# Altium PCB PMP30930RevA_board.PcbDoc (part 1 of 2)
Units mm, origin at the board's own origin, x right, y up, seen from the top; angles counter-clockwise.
Board outline 59.18 x 142.49 mm, 4 copper layers (Top Layer, Layer 1, Layer 2, Bottom Layer), stack 1.787 mm thick; 111 components, 60 nets, 253 pads, 640 vias.
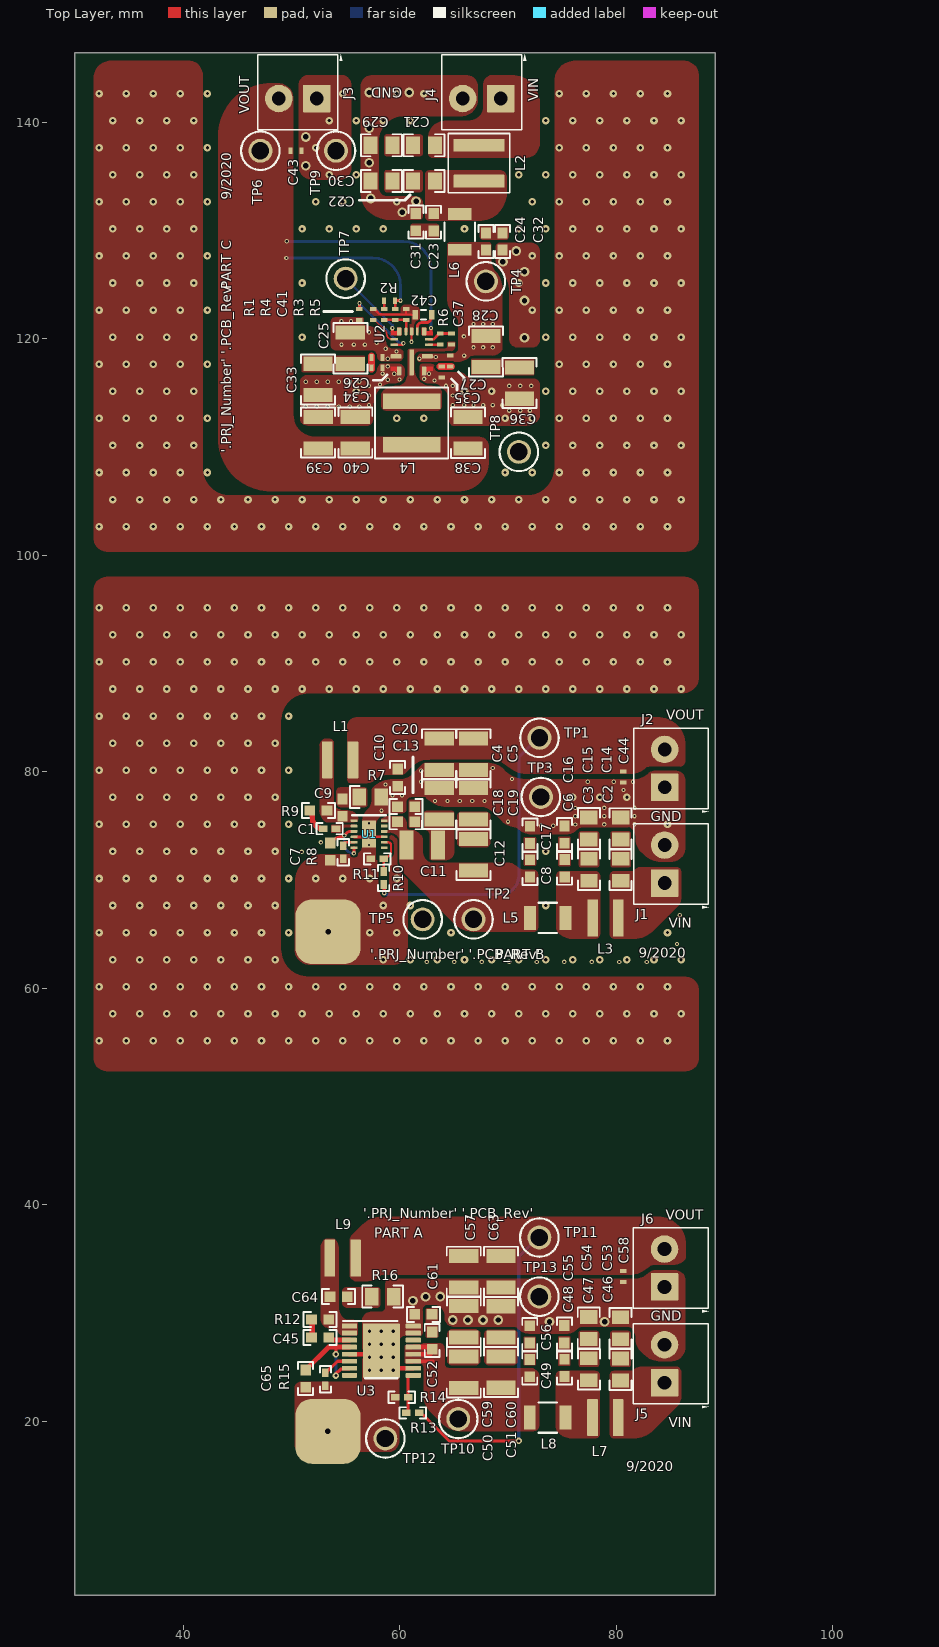
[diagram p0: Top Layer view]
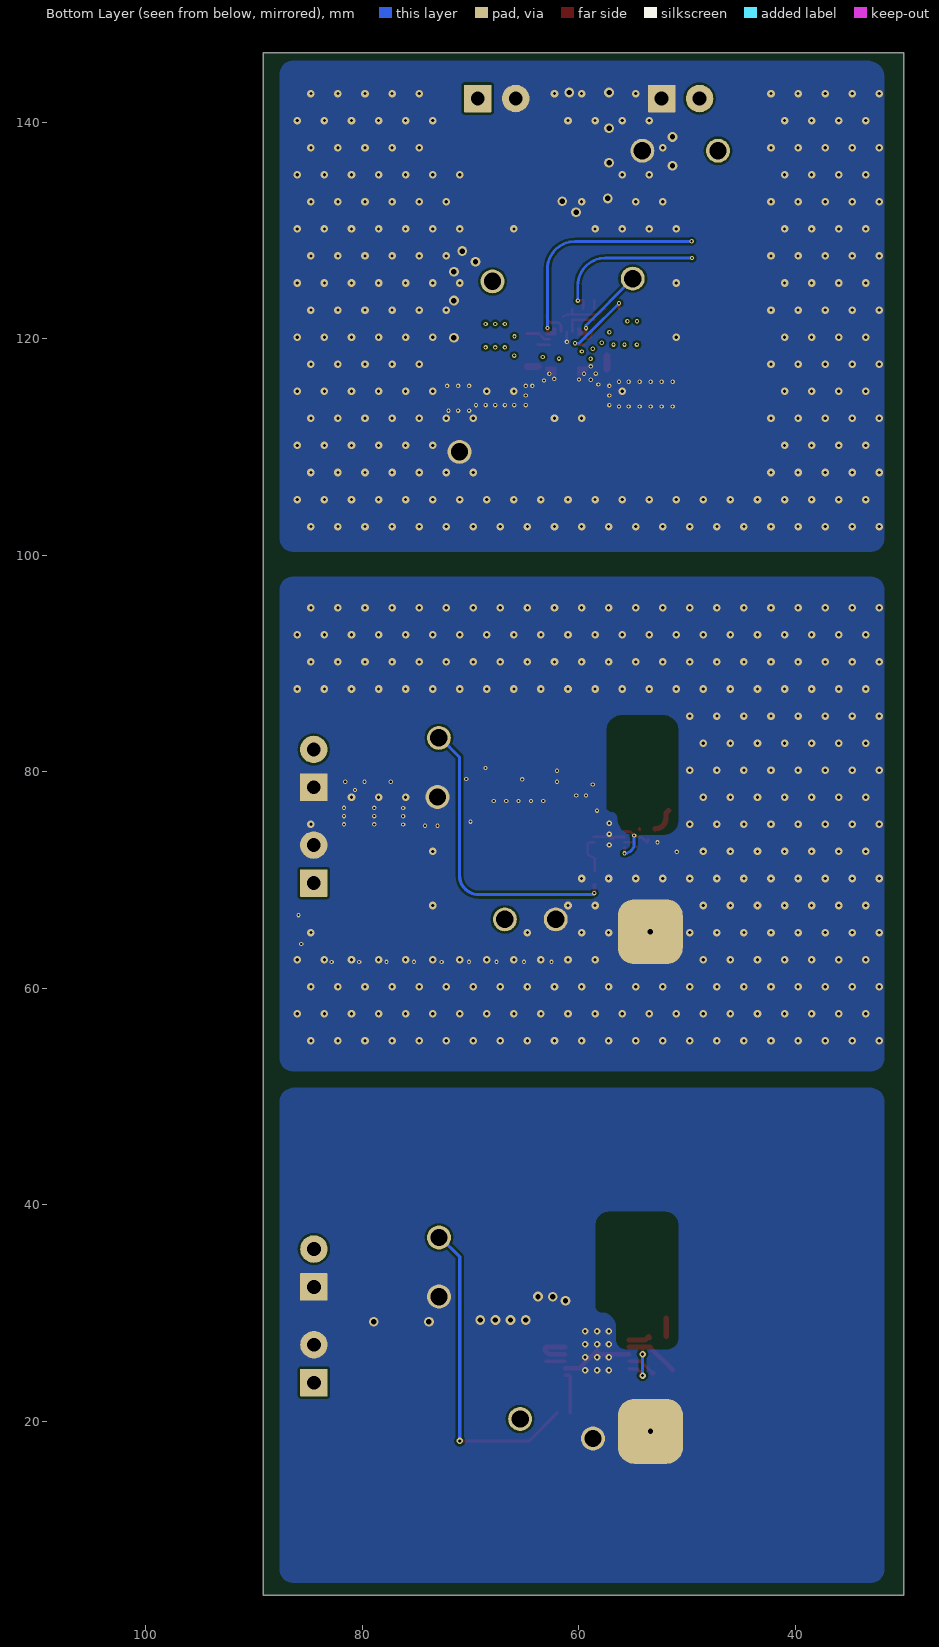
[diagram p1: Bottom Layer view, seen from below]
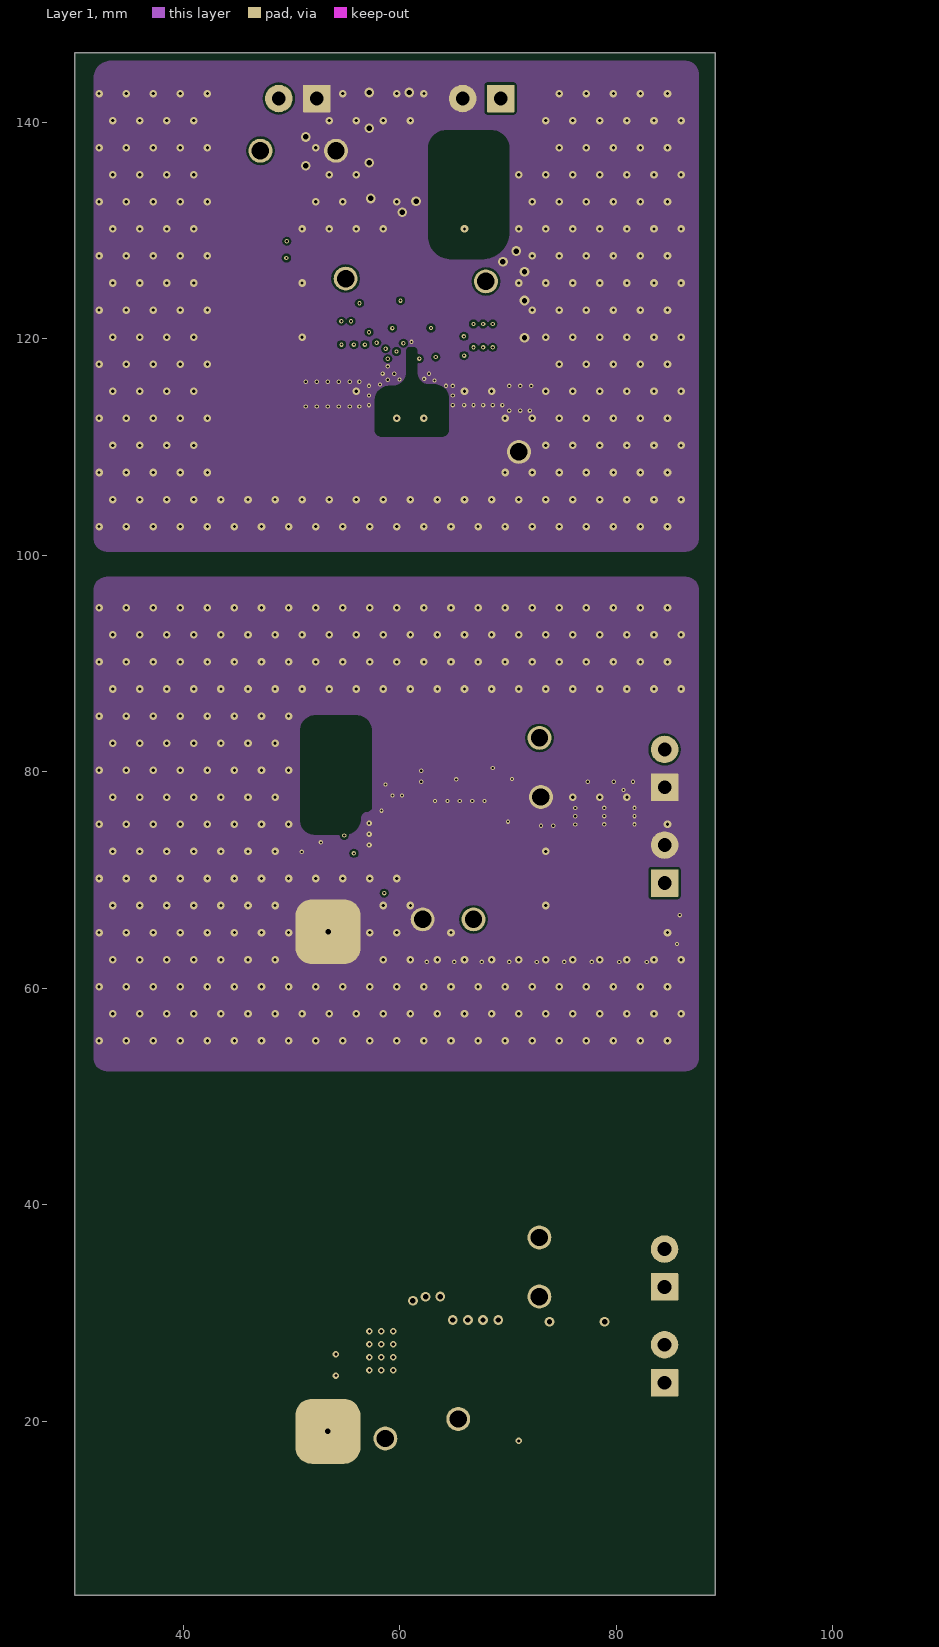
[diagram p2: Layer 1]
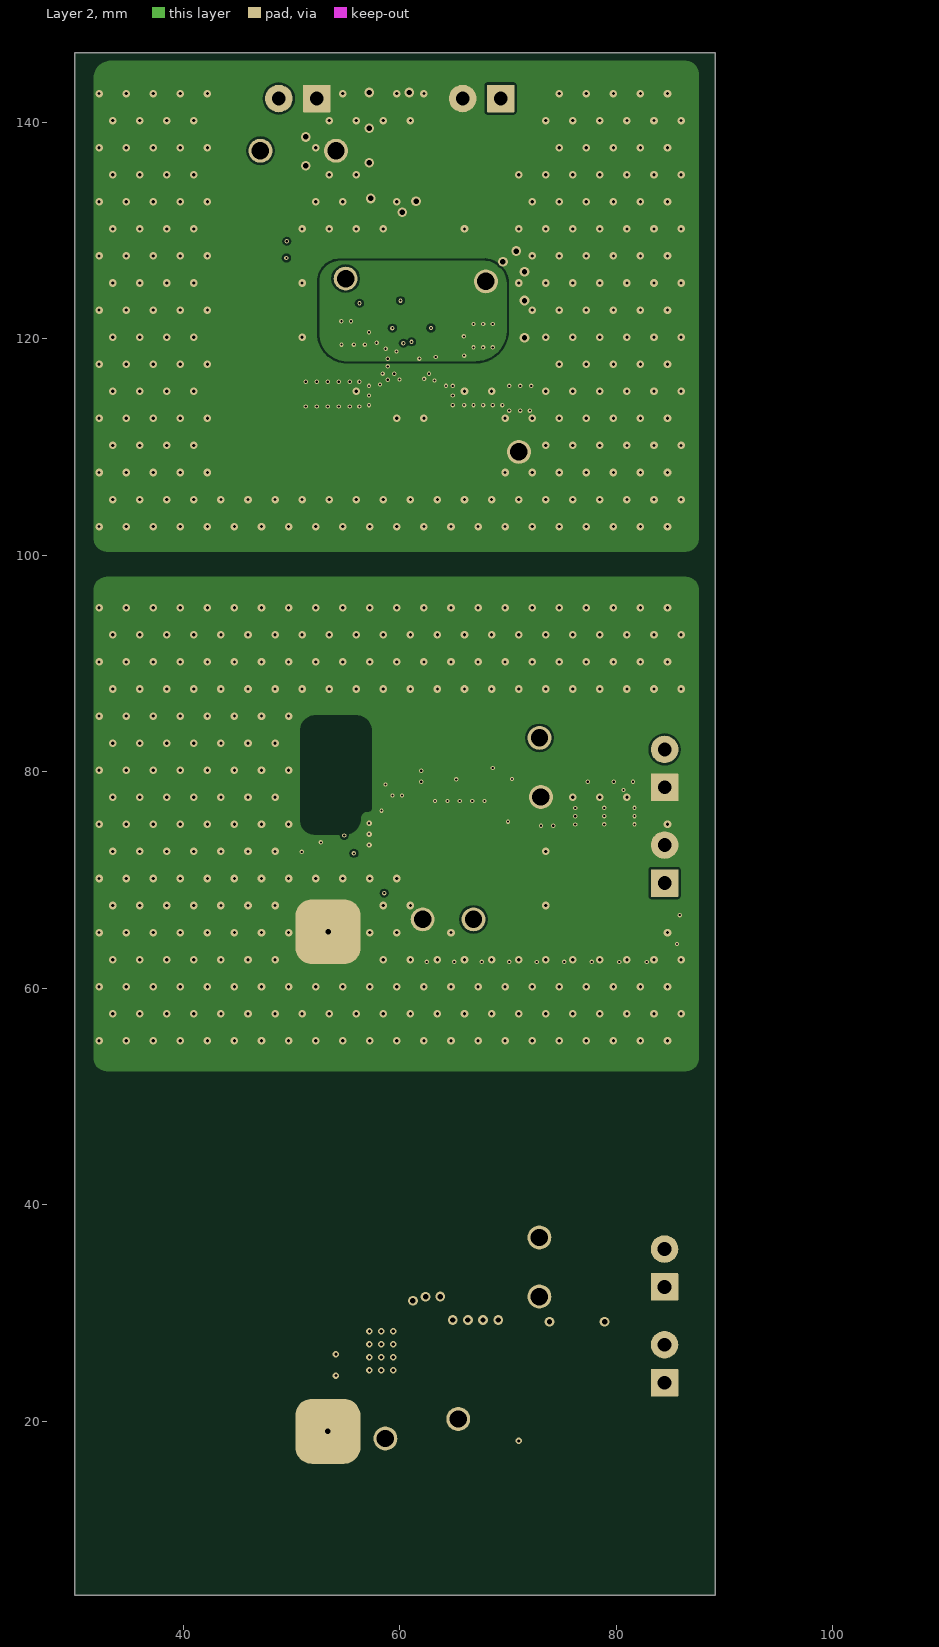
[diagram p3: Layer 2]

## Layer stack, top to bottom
Top Solder: solder mask 0.0102, Solder Resist, Dk 3.5
Top Layer: signal copper 0.0356
Dielectric 1: prepreg 0.0711, PP-006, Dk 4.1
Layer 1: signal copper 0.035
Dielectric1: core 1.5037, FR-4, Dk 4.8
Layer 2: signal copper 0.035
Dielectric 2: prepreg 0.0711, PP-006, Dk 4.1
Bottom Layer: signal copper 0.0356
Bottom Solder: solder mask 0.0102, Solder Resist, Dk 3.5

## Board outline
29.972,3.937 29.972,146.431 89.154,146.431 89.154,50.073 89.154,3.937

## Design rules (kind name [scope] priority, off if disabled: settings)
AcuteAngle [All] p1: minimum=4.50000000000000E+0001 checktracksonly=FALSE
AssemblyTestPointUsage [All] p1: valid=2
Clearance Clearance_Keepouts [((IsTrack Or IsArc) And Not InPoly) And IsFree and IsKeepOut vs ((IsTrack Or IsArc) And Not InPoly) And IsFree and IsKeepOut] p1: gap=0 ignorepadtopadclearanceinfootprint=FALSE
Clearance Clearance_BoardEdge_MountingHoles [OnCopper and InComponentClass('Mounting Holes') vs IsKeepOut] p2: gap=1.016 ignorepadtopadclearanceinfootprint=FALSE except(0: Arc-Hole Track-Hole SMDPad-Hole THPad-Hole Via-Hole Fill-Hole Poly-Hole Region-Hole Text-Hole)
Clearance Clearance_BoardEdge_Poly [OnCopper and InPoly vs IsKeepOut] p3: gap=0.635 ignorepadtopadclearanceinfootprint=FALSE except(0: Arc-Hole Track-Hole SMDPad-Hole THPad-Hole Via-Hole Fill-Hole Poly-Hole Region-Hole Text-Hole)
Clearance Clearance_BoardEdge [OnCopper and Not InComponentClass('Logo') and not InComponentClass('FiducialMark') and not InRegion(1000,500,4000,800) and Not IsKeepout vs IsKeepOut] p4: gap=1.905 ignorepadtopadclearanceinfootprint=FALSE except(0: Arc-Hole Track-Hole SMDPad-Hole THPad-Hole Via-Hole Fill-Hole Poly-Hole Region-Hole Text-Hole)
Clearance Clearance_Poly_U1 [InPolygon vs InComponent('U1')] p5: gap=0.24 ignorepadtopadclearanceinfootprint=FALSE
Clearance Clearance_Poly [InPolygon] p6: gap=0.203 ignorepadtopadclearanceinfootprint=FALSE
Clearance [All] p7: gap=0.2 ignorepadtopadclearanceinfootprint=FALSE except(0: Arc-Hole Track-Hole SMDPad-Hole THPad-Hole Via-Hole Fill-Hole Poly-Hole Region-Hole Text-Hole)
ComponentClearance ComponentClearance_MountingHoles_FiducialMarks [InComponentClass('Mounting Holes') vs InComponentClass('FiducialMark')] p1: gap=1.27 collisioncheckmode=3 verticalgap=0.254 showdistances=FALSE
ComponentClearance ComponentClearance_Shunt [InComponentClass('Header') vs InComponentClass('Shunt')] p2: gap=0 collisioncheckmode=3 verticalgap=0 showdistances=FALSE
ComponentClearance ComponentClearance_Logo [InComponentClass('Logo')] p3: gap=1.27 collisioncheckmode=3 verticalgap=0.254 showdistances=FALSE
ComponentClearance ComponentClearance_ScrewToNut [(HasFootprint('NY PMS 440 0025 PH')) vs (HasFootprint('Keystone_1902C'))] p4: gap=0.127 collisioncheckmode=3 verticalgap=0.254 showdistances=FALSE
ComponentClearance ComponentClearance_MountingHoles [InComponentClass('Mounting Holes')] p5: gap=6.35 collisioncheckmode=3 verticalgap=2540 showdistances=FALSE
ComponentClearance ComponentClearance_SmallPassives [HasFootprint('0201*') or HasFootprint('0402*') or HasFootprint('0508') or HasFootprint('0603*') or HasFootprint('0612') or HasFootprint('0805*') or HasFootprint('0815*') or HasFootprint('0830*') or HasFootprint('1206*') or HasFootprint('1210*') or HasFootprint('1808*') or HasFootprint('1812*') or HasFootprint('1825*') or HasFootprint('2010*') or HasFootprint('2220*') or HasFootprint('2225*') or HasFootprint('2512*') or HasFootprint('2728*') or HasFootprint('3518*') vs HasFootprint('0201*') or HasFootprint('0402*') or HasFootprint('0508') or HasFootprint('0603*') or HasFootprint('0612') or HasFootprint('0805*') or HasFootprint('0815*') or HasFootprint('0830*') or HasFootprint('1206*') or HasFootprint('1210*') or HasFootprint('1808*') or HasFootprint('1812*') or HasFootprint('1825*') or HasFootprint('2010*') or HasFootprint('2220*') or HasFootprint('2225*') or HasFootprint('2512*') or HasFootprint('2728*') or HasFootprint('3518*')] p6: gap=0.38 collisioncheckmode=3 verticalgap=0.254 showdistances=FALSE
ComponentClearance ComponentClearance_THtoSMT [IsThruComponent vs IsSMTComponent] p7: gap=1 collisioncheckmode=3 verticalgap=0.762 showdistances=FALSE
ComponentClearance ComponentClearance_THtoTH [IsThruComponent vs IsThruComponent] p8: gap=0.762 collisioncheckmode=3 verticalgap=0.762 showdistances=FALSE
ComponentClearance [All] p9: gap=0.762 collisioncheckmode=3 verticalgap=0.254 showdistances=FALSE
DiffPairsRouting [All] p1: maxlimit=2.54 minlimit=0.254 mostfreqgap=0.254 toplayer_minwidth=0.381 toplayer_maxwidth=0.381 toplayer_prefwidth=0.381 midlayer1_minwidth=0.381 midlayer1_maxwidth=0.381 midlayer1_prefwidth=0.381 midlayer2_minwidth=0.381 midlayer2_maxwidth=0.381 midlayer2_prefwidth=0.381 bottomlayer_minwidth=0.381 bottomlayer_maxwidth=0.381 bottomlayer_prefwidth=0.381 maxuncoupledlength=25.4
FabricationTestPointUsage TestPointUsage [All] p1: valid=2 allowmultiple=FALSE
FabricationTestpoint Testpoint [All] p1: side=3 testpointundercomponent=TRUE minsize=1.016 maxsize=2.54 preferedsize=1.524 minholesize=0 maxholesize=1.016 preferedholesize=0.813 testpointgrid=0.025 allowsidetop=TRUE allowsidebottom=TRUE usegrid=TRUE gridtolerance=0
FanoutControl Fanout_LCC [IsLCC] p1: bgadir=Out bgaviamode=Centered fanoutstyle=Auto fanoutdirection=Alternating viagrid=0.025 // Fanout_LCC (Default Rule)
FanoutControl Fanout_BGA [IsBGA] p2: bgadir=Out bgaviamode=Centered fanoutstyle=Auto fanoutdirection=Alternating viagrid=0.025 // Fanout_BGA (Default Rule)
FanoutControl Fanout_Default [All] p4: bgadir=Out bgaviamode=Centered fanoutstyle=Auto fanoutdirection=Alternating viagrid=0.025 // Fanout_Default (Default Rule)
FanoutControl Fanout_Small [(CompPinCount < 5)] p5: bgadir=Out bgaviamode=Centered fanoutstyle=Auto fanoutdirection=OutThenIn viagrid=0.025 // Fanout_Small (Default Rule)
HoleSize [All] p1: absolutevalues=TRUE maxlimit=6.375 minlimit=0.3 maxpercent=80.000 minpercent=20.000
MinimumAnnularRing MinimumAnnularRing_ThermalPadVias [IsVia and InAnyComponent] p1: minimumring=0.15
MinimumAnnularRing [All] p2: minimumring=0.15
MinimumSolderMaskSliver MinimumSolderMaskSliver_Logo [InComponentClass('Logo') vs InComponentClass('Logo')] p1: minsoldermaskwidth=0.018
MinimumSolderMaskSliver [All] p2: minsoldermaskwidth=0.1
PlaneConnect [All] p1: planeconnectstyle=Relief reliefexpansion=0.254 reliefentries=4 reliefconductorwidth=0.254 reliefairgap=0.254
PolygonConnect [All] p1: connectstyle=Direct reliefconductorwidth=0.254 reliefentries=4 polygonreliefangle="90 Angle" airgapwidth=0.254
RoutingVias ThermalPadVias [IsVia and InAnyComponent] p1: holewidth=0.2 width=0.5 viastyle="Through Hole" minholewidth=0.3 minwidth=0.6 maxholewidth=0.33 maxwidth=0.6
RoutingVias [All] p2: holewidth=0.3 width=0.6 viastyle="Through Hole" minholewidth=0.3 minwidth=0.6 maxholewidth=1.016 maxwidth=1.651
SilkToBoardRegionClearance [Not ((IsComment or IsDesignator) And (Hide <> 'False')) and not InRegion(1000,500,4000,800)] p1:
SilkToSilkClearance SilkToSilkClearance_Pb-FreeLogo [(HasFootprint('Pb-Free_Overlay_Medium') OR HasFootprint('Pb-Free_Overlay_Small')) vs (HasFootprint('Pb-Free_Overlay_Medium') OR HasFootprint('Pb-Free_Overlay_Small'))] p1: silktosilkclearance=0
SilkToSilkClearance [All] p2: silktosilkclearance=0.102
SilkToSolderMaskClearance SilkToComonentPadClearance [IsPad and InAnycomponent] p1: minsilkscreentomaskgap=0.127 clearancetoexposedcopper=TRUE
SilkToSolderMaskClearance "Silk to Solder Mask Opening" [All] p2: minsilkscreentomaskgap=0.102 clearancetoexposedcopper=FALSE
SolderMaskExpansion [All] p1: expansion=0.05 istentingtop=FALSE
Width [All] p1: maxlimit=2.54 minlimit=0.152 preferedwidth=0.254 checkconnectedcopper=TRUE
15 further rules are at their usual default settings.

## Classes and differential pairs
component class PMP30930RevA_schematic_2: C45 C46 C47 C48 C49 C50 C51 C52 C53 C54 C55 C56 C57 C58 C59 C60 C61 C62 C63 C64 C65 J5 J6 L7 L8 L9 R12 R13 R14 R15 R16 TP10 TP11 TP12 TP13 U3
component class PMP30930RevA_schematic: C1 C2 C3 C4 C5 C6 C7 C8 C9 C10 C11 C12 C13 C14 C15 C16 C17 C18 C19 C20 C21 C22 C23 C24 C25 C26 C27 C28 C29 C30 C31 C32 C33 C34 C35 C36 C37 C38 C39 C40 C41 C42 C43 C44 J1 J2 J3 J4 L1 L2 L3 L4 L5 L6 R1 R2 R3 R4 R5 R6 R7 R8 R9 R10 R11 TP1 TP2 TP3 TP4 TP5 TP6 TP7 TP8 TP9 U1 U2

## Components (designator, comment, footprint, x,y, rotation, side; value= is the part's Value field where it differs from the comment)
C1 "GCM155R71C224KE02D" 0402 53.519,74.755 r0 top value=0.22uF
C2 "CGA4J3X7R1H225K125AB" 0805_HV 80.404,70.948 r90 top value=2.2uF
C3 "CGA4J3X7R1H225K125AB" 0805_HV 77.479,70.966 r90 top value=2.2uF
C4 "GRM32ER71E226KE15L" 1210_270 63.64,81.616 r270 top value=22uF
C5 "GRM32ER71E226KE15L" 1210_270 66.815,81.616 r270 top value=22uF
C6 "06035C273K4T2A" 0603 75.23,71.093 r90 top value=0.027uF
C7 "GCM188R71E105KA64D" 0603 53.58,72.642 r270 top value=1uF
C8 "06035C273K4T2A" 0603 72.022,71.075 r90 top value=0.027uF
C9 "GRM188R71H102KA01D" 0603 54.705,76.701 r90 top value=1000pF
C10 "GRM188R71E104KA01D" 0603 59.809,79.468 r270 top value=0.1uF
C11 "GRM32ER71H106KA12L" 1210_270 62.075,73.236 r0 top value=10uF
C12 "GRM32ER71H106KA12L" 1210_270 66.815,72.345 r90 top value=10uF
C13 "CGA3E3X7R1H474K080AE" 0603 60.592,75.393 r0 top value=0.47uF
C14 "CGA4J3X7R1H225K125AB" 0805_HV 80.404,74.758 r90 top value=2.2uF
C15 "CGA4J3X7R1H225K125AB" 0805_HV 77.471,74.778 r90 top value=2.2uF
C16 "06035C273K4T2A" 0603 75.221,74.208 r90 top value=0.027uF
C17 "06035C273K4T2A" 0603 72.022,74.183 r90 top value=0.027uF
C18 "GRM32ER71H106KA12L" 1210_270 63.64,77.044 r90 top value=10uF
C19 "GRM32ER71H106KA12L" 1210_270 66.815,77.044 r90 top value=10uF
C20 "CGA3E3X7R1H474K080AE" 0603 60.592,76.79 r180 top value=0.47uF
C21 "CGA4J3X7R1H225K125AB" 0805_HV 62.243,137.877 r180 top value=2.2uF
C22 "CGA4J3X7R1H225K125AB" 0805_HV 62.243,134.575 r180 top value=2.2uF
C23 "06035C273K4T2A" 0603 63.132,130.765 r270 top value=0.027uF
C24 "06035C273K4T2A" 0603 67.958,128.987 r90 top value=0.027uF
C25 "GRM32ER71H106KA12L" 1210_270 55.436,119.128 r270 top value=10uF
C26 "CGA2B3X7R1H104K050BB" 0402S 57.897,118.273 r180 top value=0.1uF
C27 "CGA2B3X7R1H104K050BB" 0402S 64.679,117.942 r270 top value=0.1uF
C28 "GRM32ER71H106KA12L" 1210_270 67.958,118.827 r270 top value=10uF
C29 "CGA4J3X7R1H225K125AB" 0805_HV 58.306,137.877 r180 top value=2.2uF
C30 "CGA4J3X7R1H225K125AB" 0805_HV 58.306,134.575 r180 top value=2.2uF
C31 "06035C273K4T2A" 0603 61.484,130.775 r90 top value=0.027uF
C32 "06035C273K4T2A" 0603 69.482,128.987 r270 top value=0.027uF
C33 "GRM32ER71H106KA12L" 1210_270 52.451,116.244 r270 top value=10uF
C34 "CGA2B3X7R1H104K050BB" 0402S 57.901,117.325 r0 top value=0.1uF
C35 "CGA2B3X7R1H104K050BB" 0402S 63.894,116.922 r270 top value=0.1uF
C36 "GRM32ER71H106KA12L" 1210_270 71.057,115.914 r270 top value=10uF
C37 "C0402C104K4RACAUTO" 0402S 64.779,119.987 r270 top value=0.1uF
C38 "GCM32ER70J476KE19L" 1210_270 66.312,111.325 r90 top value=47uF
C39 "GCM32ER70J476KE19L" 1210_270 52.464,111.334 r90 top value=47uF
C40 "GCM32ER70J476KE19L" 1210_270 55.893,111.334 r90 top value=47uF
C41 "C0402C330J5GACAUTO" 0402S 58.56,122.256 r270 top value=33pF
C42 "GCM188R71C105KA64D" 0603S 62.189,122.219 r180 top value=1uF
C43 "CGA2B3X7R1H104K050BB" 0402S 50.432,137.369 r0 top value=0.1uF
C44 "CGA2B3X7R1H104K050BB" 0402S 80.643,79.528 r270 top value=0.1uF
C45 "GCM188R71H224KA64D" 0603 52.644,27.759 r0 top value=0.22uF
C46 "CGA4J3X7R1H225K125AB" 0805_HV 80.391,24.8 r90 top value=2.2uF
C47 "CGA4J3X7R1H225K125AB" 0805_HV 77.466,24.818 r90 top value=2.2uF
C48 "06035C273K4T2A" 0603 75.217,24.945 r90 top value=0.027uF
C49 "06035C273K4T2A" 0603 72.009,24.927 r90 top value=0.027uF
C50 "GRM32ER71H106KA12L" 1210_270 65.913,24.546 r90 top value=10uF
C51 "GRM32ER71H106KA12L" 1210_270 69.349,24.566 r90 top value=10uF
C52 "CGA3E3X7R1H474K080AE" 0603 63,27.471 r90 top value=0.47uF
C53 "CGA4J3X7R1H225K125AB" 0805_HV 80.391,28.61 r90 top value=2.2uF
C54 "CGA4J3X7R1H225K125AB" 0805_HV 77.458,28.63 r90 top value=2.2uF
C55 "06035C273K4T2A" 0603 75.208,28.06 r90 top value=0.027uF
C56 "06035C273K4T2A" 0603 72.009,28.035 r90 top value=0.027uF
C57 "GRM32ER71E226KE15L" 1210_270 65.913,33.817 r270 top value=22uF
C58 "CGA2B3X7R1H104K050BB" 0402S 80.63,33.38 r270 top value=0.1uF
C59 "GRM32ER71H106KA12L" 1210_270 65.916,29.21 r90 top value=10uF
C60 "GRM32ER71H106KA12L" 1210_270 69.341,29.191 r90 top value=10uF
C61 "CGA3E3X7R1H474K080AE" 0603 62.181,29.896 r180 top value=0.47uF
C63 "GRM32ER71E226KE15L" 1210_270 69.342,33.817 r270 top value=22uF
C64 "GRM188R71H102KA01D" 0603 54.356,31.531 r0 top value=1000pF
C65 "GCM188R71E105KA64D" 0603 51.308,23.962 r270 top value=1uF
J1 "ED555/2DS" TERM_BLK_ED555-2DS 84.468,69.729 r90 top
J2 "ED555/2DS" TERM_BLK_ED555-2DS 84.468,78.568 r90 top
J3 "ED555/2DS" TERM_BLK_ED555-2DS 52.337,142.195 r180 top
J4 "ED555/2DS" TERM_BLK_ED555-2DS 69.32,142.195 r180 top
J5 "ED555/2DS" TERM_BLK_ED555-2DS 84.455,23.581 r90 top
J6 "ED555/2DS" TERM_BLK_ED555-2DS 84.455,32.42 r90 top
L1 "XGL4020-222MEC" FP-XGL4020-222MEC_SMT_4MM0_4MM0-MFG 54.496,81.108 r0 top
L2 "XEL5030-222MEB" FP-XEL5030-222MEB_SMT_INDUCTOR_5MM28_5MM48-MFG 67.323,136.226 r270 top
L3 "XGL4020-471MEC" FP-XGL4020-471MEC_SMT_4MM0_4MM0-MFG 79.007,66.503 r180 top
L4 "XAL6060-472MEB" XAL6060 61.1,112.223 r270 top value=4.7uH
L5 "FBMH3225HM601NT" 1210_280 73.673,66.503 r180 top value="600 ohm"
L6 "FBMH3225HM601NT" 1210_280 65.545,129.876 r270 top value="600 ohm"
L7 "XGL4020-471MEC" FP-XGL4020-471MEC_SMT_4MM0_4MM0-MFG 78.994,20.355 r180 top
L8 "FBMH3225HM601NT" 1210_280 73.66,20.355 r180 top value="600 ohm"
L9 "XGL4020-222MEC" FP-XGL4020-222MEC_SMT_4MM0_4MM0-MFG 54.737,35.087 r0 top
R1 "CRCW040244K2FKED" 0402S 56.274,122.256 r270 top value=44.2k
R2 "CRCW04021K00FKED" 0402S 59.068,123.526 r0 top value=1.00k
R3 "RMCF0402FT100K" 0402S 59.576,122.256 r90 top value=100k
R4 "CRCW040239K2FKED" 0402S 57.544,122.256 r270 top value=39.2k
R5 "CRCW040224K9FKED" 0402S 60.592,122.256 r270 top value=24.9k
R6 "CRCW04020000Z0EDHP" 0402S 63.739,119.989 r270 top value=0
R7 "CRCW08052R00FKEAHP" 0805_HV 57.284,77.685 r0 top value=2.00
R8 "CRCW040210K0FKED" 0402 54.777,72.576 r90 top value=10.0k
R9 "CRCW06034R70JNEA" 0603 52.485,76.429 r180 top value=4.7
R10 "CRCW040251K1FKED" 0402 58.509,70.202 r270 top value=51.1k
R11 "CRCW040210K0FKED" 0402 57.925,71.964 r0 top value=10.0k
R12 "CRCW06034R70JNEA" 0603 52.649,29.419 r180 top value=4.7
R13 "CRCW040251K1FKED" 0402 61.216,20.79 r0 top value=51.1k
R14 "CRCW040210K0FKED" 0402 60.172,22.235 r0 top value=10.0k
R15 "CRCW040210K0FKED" 0402 53.137,23.886 r90 top value=10.0k
R16 "CRCW08052R00FKEAHP" 0805_HV 58.42,31.531 r0 top value=2.00
TP1 "5010" Keystone5010 72.911,83.14 r0 top
TP2 "5010" Keystone5010 66.815,66.376 r0 top
TP3 "5011" Keystone5011 73.038,77.679 r0 top
TP4 "5010" Keystone5010 67.958,125.304 r90 top
TP5 "5011" Keystone5011 62.116,66.376 r0 top
TP6 "5010" Keystone5010 47.13,137.369 r90 top
TP7 "5012" Keystone5012 55.004,125.558 r90 top
TP8 "5011" Keystone5011 71.006,109.556 r90 top
TP9 "5011" Keystone5011 54.115,137.369 r90 top
TP10 "5010" Keystone5010 65.405,20.228 r0 top
TP11 "5010" Keystone5010 72.898,36.992 r0 top
TP12 "5011" Keystone5011 58.674,18.425 r0 top
TP13 "5011" Keystone5011 72.898,31.531 r0 top
U1 "LM63635DQDRRRQ1" DRR0012E-MFG 57.17,74.246 r0 top
U2 "LM61460AANQRJRTQ1" RJR0014A 61.1,118.827 r270 top
U3 "LM63625DQPWPTQ1" PWP0016K_N 58.303,26.535 r0 top

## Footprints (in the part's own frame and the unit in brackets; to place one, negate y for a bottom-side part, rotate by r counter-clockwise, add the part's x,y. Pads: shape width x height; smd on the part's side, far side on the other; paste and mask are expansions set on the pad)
0402 [mm] "0402 from SM-752 data"
  rect 0.8x0.6 smd: 1(-0.6,0) 2(0.6,0)
  silkscreen extent -1.22,-0.52 1.22,0.52, body extent -0.55,-0.3 0.55,0.3, height 0.6
0402S [mil] "Based on C0402S footprint from PADS legacy"
  rect 15x24 smd: 1(-20,0) 2(20,0)
  body extent -22,-12 22,12, height 24
0603 [mm] "0603 from SM-752 data"
  rect 1x0.95 smd: 1(-0.8,0) 2(0.8,0)
  silkscreen extent -1.52,-0.69 1.52,0.69, body extent -0.87,-0.47 0.87,0.47, height 1
0603S [mil]
  rect 20x35 smd: 1(-30,0) 2(30,0)
  silkscreen extent -10,-17 10,17, body extent -34,-19 34,19, height 39
0805_HV [mil] "0805 with 30mil clearance between pads"
  rect 50x63 smd: 1(-40,0) 2(40,0)
  silkscreen extent -74,-40 74,40, body extent -43,-29 43,29, height 57
1210_270 [mm] "1210"
  rect 1.3x2.7 smd: 1(-1.45,0) 2(1.45,0)
  silkscreen extent -2.32,-1.57 2.32,1.57, body extent -1.7,-1.35 1.7,1.35, height 2.7
1210_280 [mm] "SMD, 2-Leads, Body 3.6x2.8mm, Height 2.8mm"
  rect 1.1x2.2 smd: 1(-1.65,0) 2(1.65,0)
  silkscreen extent -0.84,-1.4 0.84,1.4, body extent -1.8,-1.4 1.8,1.4, height 2.8
DRR0012E-MFG [mm]
  rrect40% 0.62x0.25 smd paste+0 mask+0: 1(-1.39,1.25) 2(-1.39,0.75) 3(-1.39,0.25) 4(-1.39,-0.25) 5(-1.39,-0.75) 6(-1.39,-1.25) 7(1.39,-1.25) 8(1.39,-0.75) 9(1.39,-0.25) 10(1.39,0.25) 11(1.39,0.75) 12(1.39,1.25)
  rrect8% 1.3x2.5 smd paste-1000 mask+0: 13(0,0)
  silkscreen extent -1.55,1.75 1.55,1.75, body extent -1.8,-1.65 1.8,1.65, height 0.25
FP-XEL5030-222MEB_SMT_INDUCTOR_5MM28_5MM48-MFG [mm]
  rrect8% 1.18x4.7 smd paste+0 mask+0: 1(-1.655,0) 2(1.655,0)
  silkscreen extent -2.74,-2.84 2.74,2.84, body extent -2.84,-2.94 2.84,2.94, height 0.25
FP-XGL4020-222MEC_SMT_4MM0_4MM0-MFG [mm]
  rrect10% 0.98x3.4 smd paste+0 mask+0: 1(-1.185,0) 2(1.185,0)
  body extent -2.25,-2.25 2.25,2.25, height 0.25
FP-XGL4020-471MEC_SMT_4MM0_4MM0-MFG [mm]
  rrect10% 0.98x3.4 smd paste+0 mask+0: 1(-1.185,0) 2(1.185,0)
  body extent -2.25,-2.25 2.25,2.25, height 0.25
Keystone5010 [mil] "Keystone Multipurpose loops"
  round 87 hole 63: 1(0,0)
  silkscreen extent -70,-70 70,70, body extent -63,-63 63,62, height 319
Keystone5011 [mil] "Keystone Multipurpose loops"
  round 87 hole 63: 1(0,0)
  silkscreen extent -70,-70 70,70, body extent -63,-63 63,62, height 319
Keystone5012 [mil] "Keystone Multipurpose loops"
  round 87 hole 63: 1(0,0)
  silkscreen extent -70,-70 70,70, body extent -63,-63 63,62, height 319
PWP0016K_N [mm] "TSSOP-16"
  rrect22% 1.4x0.45 smd: 1(-2.95,2.275) 2(-2.95,1.625) 3(-2.95,0.975) 4(-2.95,0.325) 5(-2.95,-0.325) 6(-2.95,-0.975) 7(-2.95,-1.625) 8(-2.95,-2.275) 9(2.95,-2.275) 10(2.95,-1.625) 11(2.95,-0.975) 12(2.95,-0.325) 13(2.95,0.325) 14(2.95,0.975) 15(2.95,1.625) 16(2.95,2.275)
  rrect3% 3.4x5 smd paste-1.7 mask-1.7: 17(0,0)
  rrect4% 2.46x2.31 on Top Paste: 17(0,0)
  rrect4% 2.46x2.31 on Top Solder: 17(0,0)
  silkscreen extent -3.55,-2.55 1.5,2.75, body extent -3.21,-2.5 3.21,2.5, height 1
RJR0014A [mm] "VQFN-HR-14"
  rrect25% 0.7x0.4 smd paste-0.3: 1(-1.85,1.15) 5(-1.85,-1.15)
  rrect40% 0.7x0.25 smd: 2(-1.85,0.525) 4(-1.85,-0.525)
  rrect33% 0.7x0.3 smd: 3(-1.85,0)
  rrect40% 0.25x0.7 smd: 6(-1.125,-1.6) 7(-0.625,-1.6) 13(-0.625,1.6) 14(-1.125,1.6)
  rrect25% 0.4x1 smd: 8(0.45,-1.45) 12(0.45,1.45)
  rrect25% 0.8x0.4 smd paste-0.3: 9(1.8,-1.15) 11(1.8,1.15)
  rrect25% 1.1x0.4 on Top Paste: 10(0.35,0) 10(1.65,0)
  rrect25% 2.4x0.4 smd paste-0.3: 10(1,0)
  Top Layer region: -2.2,1 -2.2,1.3 -2.196,1.319 -2.185,1.335 -2.169,1.346 -2.15,1.35 -2.15,1.35 -2.15,1.35 -1.97,1.35 -1.924,1.359 -1.885,1.385 -1.859,1.424 -1.85,1.47 -1.85,1.47 -1.85,1.9 -1.85,1.9 -1.846,1.919 -1.835,1.935 -1.819,1.946 -1.8,1.95 -1.8,1.95 -1.55,1.95 -1.531,1.946 -1.515,1.935 -1.504,1.919 -1.5,1.9 -1.5,1.9 -1.5,1 -1.504,0.981 -1.515,0.965 -1.531,0.954 -1.55,0.95 -1.55,0.95 -2.15,0.95 -2.169,0.954 -2.185,0.965 -2.196,0.981 -2.2,1
  Top Layer region: 1.4,1 1.4,1.9 1.404,1.919 1.415,1.935 1.431,1.946 1.45,1.95 1.45,1.95 1.75,1.95 1.769,1.946 1.785,1.935 1.796,1.919 1.8,1.9 1.8,1.9 1.8,1.47 1.809,1.424 1.835,1.385 1.874,1.359 1.92,1.35 1.92,1.35 2.15,1.35 2.15,1.35 2.169,1.346 2.185,1.335 2.196,1.319 2.2,1.3 2.2,1.3 2.2,1 2.196,0.981 2.185,0.965 2.169,0.954 2.15,0.95 2.15,0.95 1.45,0.95 1.431,0.954 1.415,0.965 1.404,0.981 1.4,1
  Top Layer region: 1.4,-1.9 1.404,-1.919 1.415,-1.935 1.431,-1.946 1.45,-1.95 1.45,-1.95 1.75,-1.95 1.769,-1.946 1.785,-1.935 1.796,-1.919 1.8,-1.9 1.8,-1.9 1.8,-1.47 1.809,-1.424 1.835,-1.385 1.874,-1.359 1.92,-1.35 1.92,-1.35 2.15,-1.35 2.169,-1.346 2.185,-1.335 2.196,-1.319 2.2,-1.3 2.2,-1.3 2.2,-1 2.196,-0.981 2.185,-0.965 2.169,-0.954 2.15,-0.95 2.15,-0.95 1.45,-0.95 1.431,-0.954 1.415,-0.965 1.404,-0.981 1.4,-1 1.4,-1
  Top Layer region: -2.15,-1.35 -2.169,-1.346 -2.185,-1.335 -2.196,-1.319 -2.2,-1.3 -2.2,-1.3 -2.2,-1 -2.196,-0.981 -2.185,-0.965 -2.169,-0.954 -2.15,-0.95 -2.15,-0.95 -1.55,-0.95 -1.531,-0.954 -1.515,-0.965 -1.504,-0.981 -1.5,-1 -1.5,-1 -1.5,-1.9 -1.504,-1.919 -1.515,-1.935 -1.531,-1.946 -1.55,-1.95 -1.55,-1.95 -1.8,-1.95 -1.819,-1.946 -1.835,-1.935 -1.846,-1.919 -1.85,-1.9 -1.85,-1.9 -1.85,-1.9 -1.85,-1.47 -1.859,-1.424 -1.885,-1.385 -1.924,-1.359 -1.97,-1.35 -1.97,-1.35
  body extent -2,-1.75 2,1.75, height 1
TERM_BLK_ED555-2DS [mil]
  rrect4% 100x100 hole 50: 1(0,0)
  round 100 hole 50: 2(138,0)
  silkscreen extent -93,-161 215,113, body extent -69,-150 207,106, height 323
XAL6060 [mil] "Coilcraft recommended land pattern Document 887-4 Revised 11/20/12"
  rect 56x210 smd: 1(-79.5,0) 2(79.5,0)
  silkscreen extent -129,-133 129,133, body extent -129,-133 129,133, height 240

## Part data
C1: library part CMP-0078265-1, "CAP, CERM, 0.22 µF, 16 V,+/- 10%, X7R, AEC-Q200 Grade 1, 0402", Cap_Case=0402, Manufacturer=MuRata, Supplier Part Number 1=490-10671-1-ND, TempCo=X7R, Tolerance_%=10%, Value2=16V, ValueDisplayed=0.22µF
C2 C3 C14 C15 C21 C22 C29 C30 C46 C47 C53 C54: library part CMP-0007977-2, "CAP, CERM, 2.2 uF, 50 V, +/- 10%, X7R, AEC-Q200 Grade 1, 0805", Cap_Case=0805, Manufacturer=TDK, Supplier Part Number 1=445-174216-1-ND, TempCo=X7R, Tolerance_%=10%, Value1="0.003288 ohm", Value2=50V, ValueDisplayed=2.2uF
C4 C5 C57 C63: "CAP, CERM, 22 µF, 25 V,+/- 10%, X7R, 1210", Cap_Case=1210, Manufacturer=MuRata, Supplier Part Number 1=490-5313-1-ND, TempCo=X7R, Tolerance_%=10, Value1="0.002334 ohm", Value2=25V, ValueDisplayed=22µF
C6 C8 C16 C17 C23 C24 C31 C32 C48 C49 C55 C56: library part CMP-0006804-3, "CAP, CERM, 0.027 uF, 50 V, +/- 10%, X7R, AEC-Q200 Grade 1, 0603", Cap_Case=0603, Manufacturer=AVX, Supplier Part Number 1=478-9873-1-ND, TempCo=X7R, Tolerance_%=10%, Value1=Unknown, Value2=50V, ValueDisplayed=0.027uF
C7 C65: "CAP, CERM, 1 µF, 25 V,+/- 10%, X7R, AEC-Q200 Grade 1, 0603", Cap_Case=0603, Manufacturer=MuRata, Supplier Part Number 1=490-10673-1-ND, TempCo=X7R, Tolerance_%=10, Value2=25V, ValueDisplayed=1µF
C9 C64: library part CMP-0007432-5, "CAP, CERM, 1000 pF, 50 V, +/- 10%, X7R, 0603", Cap_Case=0603, Manufacturer=MuRata, Supplier Part Number 1=490-1494-1-ND, TempCo=X7R, Tolerance_%=10%, Value1=Unknown, Value2=50V, ValueDisplayed=1000pF
C10: "CAP, CERM, 0.1 µF, 25 V,+/- 10%, X7R, 0603", Cap_Case=0603, Manufacturer=MuRata, Supplier Part Number 1=490-1524-1-ND, TempCo=X7R, Tolerance_%=10, Value2=25V, ValueDisplayed=0.1µF
C11 C12 C18 C19 C25 C28 C33 C36 C50 C51 C59 C60: library part CMP-0009226-3, "CAP, CERM, 10 uF, 50 V, +/- 10%, X7R, 1210", Cap_Case=1210, Manufacturer=MuRata, Supplier Part Number 1=490-6544-1-ND, TempCo=X7R, Tolerance_%=10%, Value1=Unknown, Value2=50V, ValueDisplayed=10uF
C13 C20 C52 C61: library part CMP-0007097-3, "CAP, CERM, 0.47 uF, 50 V, +/- 10%, X7R, AEC-Q200 Grade 1, 0603", Cap_Case=0603, Manufacturer=TDK, Supplier Part Number 1=445-172475-1-ND, TempCo=X7R, Tolerance_%=10%, Value1=Unknown, Value2=50V, ValueDisplayed=0.47uF
C26 C27 C34 C35: library part CMP-0006325-2, "CAP, CERM, 0.1 uF, 50 V, +/- 10%, X7R, AEC-Q200 Grade 1, 0402", Cap_Case=0402, Manufacturer=TDK, Supplier Part Number 1=445-6899-1-ND, TempCo=X7R, Tolerance_%=10%, Value1="0.039064 ohm", Value2=50V, ValueDisplayed=0.1uF
C37: library part CMP-0006237-1, "CAP, CERM, 0.1 uF, 16 V, +/- 10%, X7R, AEC-Q200 Grade 1, 0402", Cap_Case=0402, Manufacturer=Kemet, Supplier Part Number 1=399-6828-1-ND, TempCo=X7R, Tolerance_%=10%, Value1=Unknown, Value2=16V, ValueDisplayed=0.1uF
C38 C39 C40: library part CMP-0009172-1, "CAP, CERM, 47 uF, 6.3 V, +/- 10%, X7R, AEC-Q200 Grade 1, 1210", Cap_Case=1210, Manufacturer=MuRata, Supplier Part Number 1=490-4844-1-ND, TempCo=X7R, Tolerance_%=10%, Value1=Unknown, Value2=6.3V, ValueDisplayed=47uF
C41: library part CMP-0079151-1, "CAP, CERM, 33 pF, 50 V,+/- 5%, C0G, AEC-Q200 Grade 1, 0402", Cap_Case=0402, Manufacturer=Kemet, Supplier Part Number 1=399-12979-1-ND, TempCo=C0G, Tolerance_%=5%, Value2=50V, ValueDisplayed=33pF
C42: library part CMP-0007136-1, "CAP, CERM, 1 uF, 16 V, +/- 10%, X7R, AEC-Q200 Grade 1, 0603", Cap_Case=0603, Manufacturer=MuRata, Supplier Part Number 1=490-5241-6-ND, TempCo=X7R, Tolerance_%=10%, Value1=Unknown, Value2=16V, ValueDisplayed=1uF
C43 C44 C58: library part CMP-0006325-2, "CAP, CERM, 0.1 uF, 50 V, +/- 10%, X7R, AEC-Q200 Grade 1, 0402", Cap_Case=0402, Manufacturer=TDK, Supplier Part Number 1=445-6899-1-ND, TempCo=X7R, Tolerance_%=10%, Value1="0.039064 ohm", Value2=50V, ValueDisplayed=DNP
C45: "CAP, CERM, 0.22 µF, 50 V,+/- 10%, X7R, AEC-Q200 Grade 1, 0603", Cap_Case=0603, Manufacturer=MuRata, Supplier Part Number 1=490-5402-1-ND, TempCo=X7R, Tolerance_%=10, Value2=50V, ValueDisplayed=0.22µF
J1 J2 J3 J4 J5 J6: library part CMP-0074913-1, "Terminal Block, 3.5mm Pitch, 2x1, TH", Color=Grey, Current_A=6A, Manufacturer="On-Shore Technology", Supplier Part Number 1=ED1514-ND, Voltage_V=150V
L1 L9: library part CMP-0086519-1, "Shielded Power Inductors", Manufacturer=Coilcraft
L2: library part CMP-0089324-1, "Shielded Power Inductor XEL5030", Manufacturer=Coilcraft, Operating Temperature Range="to +165°C", Self Resonant Frequency=36MHz, Test Frequency=1MHz, Tolerance_%=20%
L3 L7: library part CMP-0087242-1, "Shielded Power Inductors", Manufacturer=Coilcraft
L4: library part CMP-0061020-1, "Inductor, Shielded, Composite, 4.7 uH, 10.5 A, 0.015 ohm, SMD", Manufacturer=Coilcraft, Value1="0.015 ohm", Value2=10.5A, ValueDisplayed=4.7uH
L5 L6 L8: library part CMP-0003374-1, "Ferrite Bead, 600 ohm @ 100 MHz, 3 A, 1210", Manufacturer="Taiyo Yuden", Supplier Part Number 1=587-1755-1-ND, Value1="0.042 ohm", Value2=3A, ValueDisplayed="600 ohm"
R1: library part CMP-0026383-2, "RES, 44.2 k, 1%, 0.063 W, AEC-Q200 Grade 0, 0402", Manufacturer=Vishay-Dale, Power_W=63mW, Supplier Part Number 1=541-44.2KLCT-ND, TempCo="100 ppm/C", Tolerance_%=1%, Value2=0.063W, Value_Code=44k2, ValueDisplayed=44.2k
R2: library part CMP-0026071-3, "RES, 1.00 k, 1%, 0.063 W, AEC-Q200 Grade 0, 0402", Manufacturer=Vishay-Dale, Power_W=63mW, Supplier Part Number 1=541-1.00KLCT-ND, TempCo="100 ppm/C", Tolerance_%=1%, Value2=0.063W, Value_Code=1k00, ValueDisplayed=1.00k
R3: library part CMP-0026753-1, "RES, 100 k, 1%, 0.063 W, AEC-Q200 Grade 0, 0402", Manufacturer="Stackpole Electronics Inc", Power_W=63mW, Supplier Part Number 1=RMCF0402FT100KCT-ND, TempCo="100 ppm/C", Tolerance_%=1%, Value2=0.063W, Value_Code=100k
R4: library part CMP-0026327-2, "RES, 39.2 k, 1%, 0.063 W, AEC-Q200 Grade 0, 0402", Manufacturer=Vishay-Dale, Power_W=63mW, Supplier Part Number 1=541-39.2KLCT-ND, TempCo="100 ppm/C", Tolerance_%=1%, Value2=0.063W, Value_Code=39k2, ValueDisplayed=39.2k
R5: library part CMP-0026196-2, "RES, 24.9 k, 1%, 0.063 W, AEC-Q200 Grade 0, 0402", Manufacturer=Vishay-Dale, Power_W=63mW, Supplier Part Number 1=541-24.9KLCT-ND, TempCo="100 ppm/C", Tolerance_%=1%, Value2=0.063W, Value_Code=24k9, ValueDisplayed=24.9k
R6: library part CMP-0081856-1, "RES, 0, 0%, 0.2 W, AEC-Q200 Grade 0, 0402", Manufacturer=Vishay-Dale, Power_W=200mW, Supplier Part Number 1=541-0.0YBTR-ND, Tolerance_%=0%, Value2=0.2W, Value_Code=0
R7 R16: library part CRCW08054R70FKEAHP, "RES, 2.00, 1%, 0.5 W, AEC-Q200 Grade 0, 0805", Manufacturer=Vishay-Dale, Power_W=0.5, Supplier Part Number 1=541-4.70TCT-ND, TempCo="100 ppm/C", Tolerance_%=1, Value1=1%, Value2=0.5W, Value_Code=2R00, ValueDisplayed=2.00
R8 R11 R14 R15: "RES, 10.0 k, 1%, 0.063 W, 0402", Manufacturer=Vishay-Dale, Power_W=0.063, Supplier Part Number 1=541-10.0KLCT-ND, TempCo="100 ppm/C", Tolerance_%=1, Value1=1%, Value2=0.063W, Value_Code=10k0, ValueDisplayed=10.0k
R9 R12: "RES, 4.7, 5%, 0.1 W, 0603", Manufacturer=Vishay-Dale, Power_W=0.1, Supplier Part Number 1=541-4.7GCT-ND, TempCo="200 ppm/C", Tolerance_%=5, Value1=5%, Value2=0.1W, Value_Code=4R70, ValueDisplayed=4.7
R10 R13: "RES, 51.1 k, 1%, 0.063 W, 0402", Manufacturer=Vishay-Dale, Power_W=0.063, Supplier Part Number 1=541-51.1KLCT-ND, TempCo="100 ppm/C", Tolerance_%=1, Value1=1%, Value2=0.063W, Value_Code=51k1, ValueDisplayed=51.1k
TP1 TP2 TP4 TP6 TP10 TP11: library part CMP-0055147-1, "Test Point, Multipurpose, Red, TH", Color=Red, Manufacturer=Keystone, Supplier Part Number 1=36-5010-ND
TP3 TP5 TP8 TP9 TP12 TP13: library part CMP-0055148-1, "Test Point, Multipurpose, Black, TH", Color=Black, Manufacturer=Keystone, Supplier Part Number 1=36-5011-ND
TP7: library part CMP-0055149-1, "Test Point, Multipurpose, White, TH", Color=White, Manufacturer=Keystone, Supplier Part Number 1=36-5012-ND
U1: library part CMP-0088353-1, "3.5-V to 36-V, 1.5-A, and 2.5-A Automotive Step-down Voltage Converter", Manufacturer="Texas Instruments", Max Supply Voltage=32V, Min Supply Voltage=3.5V, Nominal Supply Current=23uA, Operating Temperature Range="-40°C to +125°C", Output Voltage=3.3/5/1-20V, Switching Frequency=400/2100/250-2200kHz
U2: library part CMP-0079820-1, "Automotive 6-A Low Noise Synchronous Buck Regulators, RJR0014A (VQFN-HR-14)", Alternate Manufacturer="Texas Instruments"
U3: library part CMP-0080080-4, "3.5-V to 36-V, 2.5-A Synchronous Step-Down Voltage Regulator with Spread Spectrum, PWP0016D (TSSOP-16)", Alternate Manufacturer="Texas Instruments", Rating=Automotive

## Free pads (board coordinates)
  rrect50% 6x6 hole 0.5: 4(53.365,19.085) 4(53.378,65.233)

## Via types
v1: diameter 0.7, hole 0.3, Top Layer to Bottom Layer, tented both sides, 486 vias
v2: diameter 0.4, hole 0.2, Top Layer to Bottom Layer, tented both sides, 113 vias
v3: diameter 0.9, hole 0.5, Top Layer to Bottom Layer, tented both sides, 23 vias
v4: diameter 0.6, hole 0.3, Top Layer to Bottom Layer, tented both sides, 15 vias
v5: diameter 0.5, hole 0.2, Top Layer to Bottom Layer, 3 vias

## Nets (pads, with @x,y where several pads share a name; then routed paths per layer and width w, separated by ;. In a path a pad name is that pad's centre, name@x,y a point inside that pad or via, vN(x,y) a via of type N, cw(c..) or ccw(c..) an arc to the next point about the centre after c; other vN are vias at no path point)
EN/SYNC: R1.1 U2.7 | length 7
  Top Layer w0.254: R1.1@56.274,122.764 56.277,122.767 v2(56.277,123.278) ; U2.7@59.5,119.452 59.502,119.454 60.203,119.454 v2(60.338,119.589)
  Bottom Layer w0.254: v2@56.274,123.272 58.948,120.603 ccw(c59.32,120.976) 58.973,120.579 59.964,119.589 v2(60.338,119.589)
GND: C4.2 C5.2 C7.2 C10.2 C14.2 C15.2 C16.2 C17.2 C18.2 C19.2 C20.2 C44.2 J1.2 J2.1 pad.4@53.378,65.233 R7.2 R8.1 R11.1 TP3.1 TP5.1 U1.4 U1.9 U1.13 | length 2.9
  Top Layer w0.203: U1.9@58.56,73.996 U1.9@58.687,73.996
  Top Layer w0.254: U1.4@55.78,73.988 U1.13@56.65,73.988 ; v5(57.17,74.246) ccw(c57.42,74.246) 57.42,73.996 U1.9@58.433,73.996
  Top Layer w0.45: U1.13@56.845,73.913 ccw(c56.845,74.238) U1.13@57.17,74.238
  other v1: 32.232,55.153 34.732,55.153 37.232,55.153 39.732,55.153 42.232,55.153 44.732,55.153 47.232,55.153 49.732,55.153 52.232,55.153 54.732,55.153 57.232,55.153 59.732,55.153 62.232,55.153 64.732,55.153 67.232,55.153 69.732,55.153 72.232,55.153 74.732,55.153 77.232,55.153 79.732,55.153 82.232,55.153 84.732,55.153 33.482,57.653 35.982,57.653 38.482,57.653 40.982,57.653 43.482,57.653 45.982,57.653 48.482,57.653 50.982,57.653 53.482,57.653 55.982,57.653 58.482,57.653 60.982,57.653 63.482,57.653 65.982,57.653 68.482,57.653 70.982,57.653 73.482,57.653 75.982,57.653 78.482,57.653 80.982,57.653 83.482,57.653 85.982,57.653 32.232,60.153 34.732,60.153 37.232,60.153 39.732,60.153 42.232,60.153 44.732,60.153 47.232,60.153 49.732,60.153 52.232,60.153 54.732,60.153 57.232,60.153 59.732,60.153 62.232,60.153 64.732,60.153 67.232,60.153 69.732,60.153 72.232,60.153 74.732,60.153 77.232,60.153 79.732,60.153 82.232,60.153 84.732,60.153 33.482,62.653 35.982,62.653 38.482,62.653 40.982,62.653 43.482,62.653 45.982,62.653 48.482,62.653 58.482,62.653 60.982,62.653 63.482,62.653 65.982,62.653 68.482,62.653 70.982,62.653 73.482,62.653 75.982,62.653 78.482,62.653 80.982,62.653 83.482,62.653 85.982,62.653 32.232,65.153 34.732,65.153 37.232,65.153 39.732,65.153 42.232,65.153 44.732,65.153 47.232,65.153 49.732,65.153 57.232,65.153 59.732,65.153 64.732,65.153 84.732,65.153 33.482,67.653 35.982,67.653 38.482,67.653 40.982,67.653 43.482,67.653 45.982,67.653 48.482,67.653 58.482,67.653 60.982,67.653 73.482,67.653 32.232,70.153 34.732,70.153 37.232,70.153 39.732,70.153 42.232,70.153 44.732,70.153 47.232,70.153 49.732,70.153 52.232,70.153 54.732,70.153 57.232,70.153 59.732,70.153 33.482,72.653 35.982,72.653 38.482,72.653 40.982,72.653 43.482,72.653 45.982,72.653 48.482,72.653 73.482,72.653 32.232,75.153 34.732,75.153 37.232,75.153 39.732,75.153 42.232,75.153 44.732,75.153 47.232,75.153 49.732,75.153 84.732,75.153 33.482,77.653 35.982,77.653 38.482,77.653 40.982,77.653 43.482,77.653 45.982,77.653 48.482,77.653 75.982,77.653 78.482,77.653 80.982,77.653 32.232,80.153 34.732,80.153 37.232,80.153 39.732,80.153 42.232,80.153 44.732,80.153 47.232,80.153 49.732,80.153 33.482,82.653 35.982,82.653 38.482,82.653 40.982,82.653 43.482,82.653 45.982,82.653 48.482,82.653 32.232,85.153 34.732,85.153 37.232,85.153 39.732,85.153 42.232,85.153 44.732,85.153 47.232,85.153 49.732,85.153 33.482,87.653 35.982,87.653 38.482,87.653 40.982,87.653 43.482,87.653 45.982,87.653 48.482,87.653 50.982,87.653 53.482,87.653 55.982,87.653 58.482,87.653 60.982,87.653 63.482,87.653 65.982,87.653 68.482,87.653 70.982,87.653 73.482,87.653 75.982,87.653 78.482,87.653 80.982,87.653 83.482,87.653 85.982,87.653 32.232,90.153 34.732,90.153 37.232,90.153 39.732,90.153 42.232,90.153 44.732,90.153 47.232,90.153 49.732,90.153 52.232,90.153 54.732,90.153 57.232,90.153 59.732,90.153 62.232,90.153 64.732,90.153 67.232,90.153 69.732,90.153 72.232,90.153 74.732,90.153 77.232,90.153 79.732,90.153 82.232,90.153 84.732,90.153 33.482,92.653 35.982,92.653 38.482,92.653 40.982,92.653 43.482,92.653 45.982,92.653 48.482,92.653 50.982,92.653 53.482,92.653 55.982,92.653 58.482,92.653 60.982,92.653 63.482,92.653 65.982,92.653 68.482,92.653 70.982,92.653 73.482,92.653 75.982,92.653 78.482,92.653 80.982,92.653 83.482,92.653 85.982,92.653 32.232,95.153 34.732,95.153 37.232,95.153 39.732,95.153 42.232,95.153 44.732,95.153 47.232,95.153 49.732,95.153 52.232,95.153 54.732,95.153 57.232,95.153 59.732,95.153 62.232,95.153 64.732,95.153 67.232,95.153 69.732,95.153 72.232,95.153 74.732,95.153 77.232,95.153 79.732,95.153 82.232,95.153 84.732,95.153
  other v2: 62.501,62.449 65.041,62.449 67.581,62.449 70.121,62.449 72.657,62.439 75.201,62.449 77.741,62.449 80.277,62.439 82.817,62.439 85.615,64.1 85.869,66.767 50.944,72.609 52.718,73.488 73.042,75.022 74.185,75.022 76.213,75.139 78.884,75.149 81.678,75.149 69.994,75.403 76.213,75.901 78.884,75.911 81.678,75.911 58.31,76.419 76.213,76.663 78.884,76.673 81.678,76.673 63.263,77.308 64.406,77.308 65.549,77.308 66.692,77.308 67.835,77.308 59.326,77.816 60.215,77.816 80.662,78.324 58.691,78.832 61.993,79.086 77.36,79.086 79.773,79.086 81.551,79.086 65.217,79.303 70.375,79.34 61.993,80.102 68.597,80.356
  other v5: 57.17,73.246 57.17,75.246
GND_B: C29.2 C30.2 C31.2 C32.2 C33.2 C34.2 C35.2 C36.2 C38.2 C39.2 C40.2 C42.2 C43.2 J3.1 J4.2 R4.1 R5.1 TP8.1 TP9.1 U2.3 U2.9 U2.11 | length 5.7
  Top Layer w0.203: R4.1@57.544,122.764 cw(c57.544,122.457) 57.761,122.674 cw(c57.617,122.53) 57.769,122.665 58.029,122.373 ccw(c58.255,122.573) 58.035,122.367 ccw(c58.255,122.573) 58.241,122.272 58.56,122.256 60.592,122.256 ; R5.1@60.592,122.764 60.592,122.256 ; v2@61.1,119.716 U2.3@61.1,120.677 ; C42.2@61.481,122.002 ccw(c60.868,121.389) 60.868,122.256 60.592,122.256
  other v1: 32.232,102.653 34.732,102.653 37.232,102.653 39.732,102.653 42.232,102.653 44.732,102.653 47.232,102.653 49.732,102.653 52.232,102.653 54.732,102.653 57.232,102.653 59.732,102.653 62.232,102.653 64.732,102.653 67.232,102.653 69.732,102.653 72.232,102.653 74.732,102.653 77.232,102.653 79.732,102.653 82.232,102.653 84.732,102.653 33.482,105.153 35.982,105.153 38.482,105.153 40.982,105.153 43.482,105.153 45.982,105.153 48.482,105.153 50.982,105.153 53.482,105.153 55.982,105.153 58.482,105.153 60.982,105.153 63.482,105.153 65.982,105.153 68.482,105.153 70.982,105.153 73.482,105.153 75.982,105.153 78.482,105.153 80.982,105.153 83.482,105.153 85.982,105.153 32.232,107.653 34.732,107.653 37.232,107.653 39.732,107.653 42.232,107.653 69.732,107.653 72.232,107.653 74.732,107.653 77.232,107.653 79.732,107.653 82.232,107.653 84.732,107.653 33.482,110.153 35.982,110.153 38.482,110.153 40.982,110.153 73.482,110.153 75.982,110.153 78.482,110.153 80.982,110.153 83.482,110.153 85.982,110.153 32.232,112.653 34.732,112.653 37.232,112.653 39.732,112.653 42.232,112.653 59.732,112.653 62.232,112.653 69.732,112.653 72.232,112.653 74.732,112.653 77.232,112.653 79.732,112.653 82.232,112.653 84.732,112.653 33.482,115.153 35.982,115.153 38.482,115.153 40.982,115.153 55.982,115.153 65.982,115.153 68.482,115.153 73.482,115.153 75.982,115.153 78.482,115.153 80.982,115.153 83.482,115.153 85.982,115.153 32.232,117.653 34.732,117.653 37.232,117.653 39.732,117.653 42.232,117.653 74.732,117.653 77.232,117.653 79.732,117.653 82.232,117.653 84.732,117.653 33.482,120.153 35.982,120.153 38.482,120.153 40.982,120.153 50.982,120.153 73.482,120.153 75.982,120.153 78.482,120.153 80.982,120.153 83.482,120.153 85.982,120.153 32.232,122.653 34.732,122.653 37.232,122.653 39.732,122.653 42.232,122.653 72.232,122.653 74.732,122.653 77.232,122.653 79.732,122.653 82.232,122.653 84.732,122.653 33.482,125.153 35.982,125.153 38.482,125.153 40.982,125.153 50.982,125.153 70.982,125.153 73.482,125.153 75.982,125.153 78.482,125.153 80.982,125.153 83.482,125.153 85.982,125.153 32.232,127.653 34.732,127.653 37.232,127.653 39.732,127.653 42.232,127.653 72.232,127.653 74.732,127.653 77.232,127.653 79.732,127.653 82.232,127.653 84.732,127.653 33.482,130.153 35.982,130.153 38.482,130.153 40.982,130.153 50.982,130.153 53.482,130.153 55.982,130.153 58.482,130.153 65.982,130.153 70.982,130.153 73.482,130.153 75.982,130.153 78.482,130.153 80.982,130.153 83.482,130.153 85.982,130.153 32.232,132.653 34.732,132.653 37.232,132.653 39.732,132.653 42.232,132.653 52.232,132.653 54.732,132.653 59.732,132.653 72.232,132.653 74.732,132.653 77.232,132.653 79.732,132.653 82.232,132.653 84.732,132.653 33.482,135.153 35.982,135.153 38.482,135.153 40.982,135.153 53.482,135.153 55.982,135.153 70.982,135.153 73.482,135.153 75.982,135.153 78.482,135.153 80.982,135.153 83.482,135.153 85.982,135.153 32.232,137.653 34.732,137.653 37.232,137.653 39.732,137.653 42.232,137.653 52.232,137.653 74.732,137.653 77.232,137.653 79.732,137.653 82.232,137.653 84.732,137.653 33.482,140.153 35.982,140.153 38.482,140.153 40.982,140.153 53.482,140.153 55.982,140.153 58.482,140.153 60.982,140.153 73.482,140.153 75.982,140.153 78.482,140.153 80.982,140.153 83.482,140.153 85.982,140.153 32.232,142.653 34.732,142.653 37.232,142.653 39.732,142.653 42.232,142.653 54.732,142.653 59.732,142.653 62.232,142.653 74.732,142.653 77.232,142.653 79.732,142.653 82.232,142.653 84.732,142.653
  other v2: 70.117,113.367 71.133,113.367 72.022,113.367 51.321,113.748 52.337,113.748 53.353,113.748 54.369,113.748 55.385,113.748 56.274,113.748 57.163,113.875 64.891,113.875 65.945,113.875 66.815,113.875 67.704,113.875 68.593,113.875 69.482,113.875 57.163,114.764 64.891,114.764 57.163,115.653 64.275,115.653 64.891,115.653 70.117,115.653 71.133,115.653 72.149,115.653 58.179,115.78 51.321,116.034 52.337,116.034 53.353,116.034 54.369,116.034 55.385,116.034 56.274,116.034 63.205,116.154 58.886,116.219 59.971,116.245 62.253,116.299 59.5,116.777 62.705,116.771 58.417,116.787 58.888,117.453 61.088,119.715
  other v3: 71.521,120.102 71.521,123.531 71.521,126.198 69.528,127.128 70.759,128.103 60.236,131.698 61.506,132.714 57.315,132.968 51.328,135.977 57.188,136.27 51.328,138.644 57.188,139.445 57.188,142.747 60.871,142.747
GND_C: C53.2 C54.2 C55.2 C56.2 C57.2 C58.2 C59.2 C60.2 C61.2 C63.2 C65.2 J5.2 J6.1 pad.4@53.365,19.085 R14.1 R15.1 R16.2 TP12.1 TP13.1 U3.5 U3.10 U3.15 U3.16 U3.17@58.303,26.535 | length 6.8
  Top Layer w0.45: U3.5@55.353,26.21 57.978,26.21 ccw(c57.978,26.535) U3.17@58.303,26.535 59.928,24.91 U3.10@61.253,24.91
  other v3: 73.831,29.22 78.918,29.215 64.897,29.372 66.294,29.372 67.691,29.372 69.088,29.372 61.214,31.15 62.39,31.53 63.752,31.536
  other v4: 57.203,24.735 58.303,24.735 59.403,24.735 57.203,25.935 58.303,25.935 59.403,25.935 57.203,27.135 58.303,27.135 59.403,27.135 57.203,28.335 58.303,28.335 59.403,28.335
NetC1_1: C1.1 R9.2 | length 2.3
  Top Layer w0.5: R9.2@51.685,76.429 51.929,76.185 51.929,75.745 ccw(c52.919,75.745) C1.1@52.919,74.755
NetC1_2: C1.2 U1.2 | length 0.1
  Top Layer w0.254: C1.2@54.381,74.659 C1.2@54.381,74.766
NetC2_1: C2.1 J1.1 L3.1
NetC2_2: C2.2 C14.1
NetC3_1: C3.1 C6.1 L3.2 L5.1
NetC3_2: C3.2 C15.1
NetC4_1: C4.1 C5.1 C10.1 C44.1 J2.2 L1.2 R10.2 TP1.1 | length 27.8
  Top Layer w0.3: R10.2@58.509,69.602 cw(c58.509,69.551) 58.56,69.551 v2@58.56,68.916
  Bottom Layer w0.3: v2(58.564,68.799) 58.591,68.799 58.728,68.662 69.228,68.662 ccw(c69.228,70.44) 71.006,70.44 71.006,81.362 72.784,83.14 TP1.1@72.911,83.14
NetC6_2: C6.2 C16.1
NetC7_1: C7.1 U1.3 U1.6 | length 5.3
  Top Layer w0.254: C7.1@53.562,73.644 C7.1@53.562,73.754 ; C7.1@53.653,73.488 ccw(c53.653,73.571) C7.1@53.711,73.512 ; C7.1@53.711,73.512 53.983,73.783 cw(c54.496,73.27) 54.496,73.996 ccw(c54.496,74.609) 54.929,74.176 55.131,74.377 cw(c55.399,74.109) 55.399,74.488 U1.3@55.78,74.488 ; v2(55.766,72.473) 55.766,72.954 cw(c55.814,72.954) U1.6@55.78,72.988
  Bottom Layer w0.254: v2(54.877,74.124) 54.877,73.362 ccw(c55.766,73.362) v2(55.766,72.473)
NetC8_1: C8.1 C11.1 C12.1 C13.1 L5.2 TP2.1 U1.10 U1.12
NetC8_2: C8.2 C17.1
NetC9_1: C9.1 L1.1 R9.1 U1.1
NetC9_2: C9.2 R7.1
NetC11_2: C11.2 C18.1
NetC12_2: C12.2 C19.1
NetC13_2: C13.2 C20.1
NetC21_1: C21.1 J4.1 L2.1
NetC21_2: C21.2 C29.1
NetC22_1: C22.1 C23.1 L2.2 L6.1
NetC22_2: C22.2 C30.1
NetC23_2: C23.2 C31.1
NetC24_1: C24.1 C25.1 C26.1 C27.1 C28.1 L6.2 R1.2 TP4.1 U2.8 U2.12
  other v2: 58.894,118.151 61.812,118.165 63.323,118.313 65.945,118.447 59.703,118.828 58.697,119.078 66.815,119.209 67.704,119.209 68.593,119.209 54.623,119.463 55.766,119.463 56.782,119.463 57.864,119.631 65.926,120.225 57.163,120.606 66.815,121.368 67.704,121.368 68.593,121.368 54.611,121.62 55.5,121.62
NetC24_2: C24.2 C32.1
NetC25_2: C25.2 C33.1
NetC26_2: C26.2 C34.1 | length 1.2
  Top Layer w0.635: C34.1@57.393,117.183 C34.1@57.393,117.325 57.394,118.273 C26.2@57.394,118.417
NetC27_2: C27.2 C35.1 | length 2.6
  Top Layer w0.635: C35.1@63.694,117.432 C27.2@64.449,117.432 ; C35.1@63.808,117.431 63.809,117.43 C27.2@64.776,117.43 ; C35.1@63.894,117.43 C27.2@64.783,117.43
NetC28_2: C28.2 C36.1
NetC37_1: C37.1 R6.1 U2.14 | length 2.3
  Top Layer w0.254: U2.14@62.7,119.952 62.702,119.954 63.128,119.954 63.652,120.478 63.767,120.478 C37.1@64.783,120.478
NetC38_1: C38.1 C39.1 C40.1 C43.1 J3.2 L4.2 R2.2 R3.2 TP6.1 U2.1 | length 35.5
  Top Layer w0.254: R3.2@59.576,122.764 R2.2@59.576,123.526 v2@60.084,123.526 ; 62.751,120.478 62.878,120.478 v2@62.878,120.986
  Bottom Layer w0.254: v2@49.543,127.463 57.532,127.463 cw(c57.532,124.923) 60.072,124.923 v2(60.072,123.525) ; v2@49.591,128.984 49.591,128.987 60.341,128.987 cw(c60.341,126.447) 62.881,126.447 v2(62.881,120.992)
  other v2: 49.531,127.462 49.568,129.005
NetC41_1: C41.1 R2.1 | length 0.8
  Top Layer w0.254: C41.1@58.56,122.764 R2.1@58.56,123.526
NetC41_2: C41.2 R3.1 R5.2 U2.4 | length 3.1
  Top Layer w0.254: C41.2@58.56,121.748 R3.1@59.576,121.748 R5.2@60.592,121.748 60.592,120.915 60.575,120.898 U2.4@60.575,120.677
NetC45_1: C45.1 R12.2 | length 1.7
  Top Layer w0.5: C45.1@51.905,27.848 R12.2@51.905,29.55
NetC45_2: C45.2 U3.3 | length 2.1
  Top Layer w0.45: C45.2@53.428,27.693 C45.2@53.504,27.769 ; C45.2@53.505,27.848 53.53,27.848 53.868,27.51 54.506,27.51 U3.3@55.353,27.51
NetC46_1: C46.1 J5.1 L7.1
NetC46_2: C46.2 C53.1
NetC47_1: C47.1 C48.1 L7.2 L8.1
NetC47_2: C47.2 C54.1
NetC48_2: C48.2 C55.1
NetC49_1: C49.1 C50.1 C51.1 C52.1 L8.2 TP10.1 U3.11 U3.12 U3.13 | length 5.9
  Top Layer w0.3: U3.11@61.253,25.56 63.068,25.56
  Top Layer w0.45: U3.12@61.253,26.21 62.588,26.21 ccw(c62.588,26.751) 63.129,26.751 63.02,26.86 U3.13@61.253,26.86
NetC49_2: C49.2 C56.1
NetC50_2: C50.2 C59.1
NetC51_2: C51.2 C60.1
NetC52_2: C52.2 C61.1
NetC57_1: C57.1 C58.1 C63.1 J6.2 L9.2 R13.2 TP11.1 | length 29.8
  Top Layer w0.3: R13.2@61.966,20.787 64.557,18.196 v4(70.993,18.196)
  Bottom Layer w0.3: v4(70.993,18.196) 70.993,35.214 72.771,36.992 TP11.1@72.898,36.992
NetC64_1: C64.1 L9.1 R12.1 U3.1 U3.2
NetC64_2: C64.2 R16.1
NetC65_1: C65.1 U3.4 U3.7 | length 9.2
  Top Layer w0.3: v4(54.102,24.241) 54.102,24.4 54.537,24.835 55.353,24.835 U3.7@55.353,24.91 ; v4(54.102,26.197) 54.102,26.86
  Top Layer w0.45: C65.1@51.308,24.762 51.32,24.762 53.419,26.86 54.102,26.86 U3.4@55.353,26.86
  Bottom Layer w0.3: v4(54.102,24.241) v4(54.102,26.197)
NetR6_2: R6.2 U2.13 | length 1.1
  Top Layer w0.254: U2.13@62.7,119.452 63.743,119.452 ccw(c63.743,119.486) R6.2@63.767,119.462
NetR8_2: R8.2 U1.5 | length 1.2
  Top Layer w0.254: R8.2@54.678,73.087 ccw(c54.678,73.578) R8.2@54.861,73.123 ; R8.2@54.827,73.418 cw(c54.996,73.249) 54.996,73.488 U1.5@55.78,73.488
NetR10_1: R10.1 R11.2 U1.8 | length 3.3
  Top Layer w0.203: R10.1@58.509,70.802 58.519,70.802 R11.2@58.519,71.964 ; U1.8@58.56,73.496 58.933,73.496 cw(c58.933,73.234) 59.195,73.234 59.195,72.61 cw(c58.75,72.61) R11.2@58.75,72.165
  Top Layer w0.3: R11.2@58.519,71.964 R11.2@58.525,71.964
NetR13_1: R13.1 R14.2 U3.9 | length 3.9
  Top Layer w0.3: R13.1@60.766,20.787 60.766,22.235 R14.2@60.772,22.235 60.772,24.185 60.847,24.26 U3.9@61.253,24.26
NetR15_2: R15.2 U3.6 | length 2.7
  Top Layer w0.3: R15.2@53.178,24.486 54.252,25.56 U3.6@55.353,25.56
  Top Layer w0.45: R15.2@53.137,24.486 R15.2@53.178,24.486
NetTP7_1: TP7.1 U2.5 | length 6.7
  Top Layer w0.254: 59.322,120.605 v2(59.322,120.986)
  Bottom Layer w0.254: TP7.1@55.004,125.558 59.322,121.24 v2(59.322,120.986)
RT: R4.2 U2.6 | length 2.8
  Top Layer w0.152: R4.2@57.723,121.695 58.634,120.785 cw(c58.201,120.351) 58.803,120.464 ; 58.814,120.351 ccw(c58.201,120.351) 58.803,120.464 ; U2.6@59.5,119.952 59.291,119.952 cw(c59.291,120.447) 58.941,120.097 cw(c59.247,120.404) 58.814,120.404 ccw(c58.634,120.404) 58.803,120.464
SW: C37.2 L4.1 U2.10@61.1,117.827
VCC: C42.1 U2.2 | length 2.5
  Top Layer w0.254: U2.2@61.625,120.677 61.625,121.101 cw(c62,121.101) 61.735,121.367 cw(c62.041,121.06) 62.041,121.494 62.444,121.494 ccw(c62.444,121.928) 62.751,121.621 ccw(c62.266,122.105) 62.951,122.105 C42.1@62.951,122.219
pads on no net: U1.7 U1.11 U2.10@61.1,117.177 U2.10@61.1,118.477 U3.8 U3.14 U3.17@58.303,26.535

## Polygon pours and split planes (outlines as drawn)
GND_B on Top Layer "NONET_L-01_P-001" (solid, pour order 160): 31.75,144.145 cw(c33.274,144.145) 33.274,145.669 40.513,145.669 cw(c40.513,144.399) 41.783,144.399 41.783,108.077 ccw(c44.323,108.077) 44.323,105.537 71.755,105.537 ccw(c71.755,108.077) 74.295,108.077 74.295,143.764 cw(c76.2,143.764) 76.2,145.669 86.233,145.669 cw(c86.233,144.272) 87.63,144.272 87.63,101.6 cw(c86.36,101.6) 86.36,100.33 33.02,100.33 cw(c33.02,101.6) 31.75,101.6
GND on Top Layer "NONET_L-01_P-001" (solid, pour order 159): 87.63,59.817 ccw(c86.36,59.817) 86.36,61.087 51.562,61.087 cw(c51.562,63.627) 49.022,63.627 49.022,84.709 cw(c51.562,84.709) 51.562,87.249 86.106,87.249 ccw(c86.106,88.773) 87.63,88.773 87.63,96.647 ccw(c86.233,96.647) 86.233,98.044 33.02,98.044 ccw(c33.02,96.774) 31.75,96.774 31.75,53.594 ccw(c33.02,53.594) 33.02,52.324 86.36,52.324 ccw(c86.36,53.594) 87.63,53.594
NetC57_1 on Top Layer "NETC57_1_L01_P149" (solid, pour order 149): 58.348,38.897 ccw(c58.348,36.357) 56.552,38.153 55.59,37.191 ccw(c56.117,36.665) 55.372,36.665 55.372,33.489 ccw(c55.805,33.489) 55.499,33.182 ccw(c56.112,33.795) 56.112,32.928 56.939,32.928 ccw(c56.939,34.663) 58.166,33.436 cw(c58.472,33.129) 58.472,33.563 81.244,33.563 ccw(c81.244,36.103) 83.04,34.307 83.058,34.325 cw(c83.364,34.018) 83.364,34.452 85.313,34.452 ccw(c85.313,35.753) 86.233,34.833 ccw(c85.745,35.321) 86.435,35.321 86.435,36.357 ccw(c83.895,36.357) 83.895,38.897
